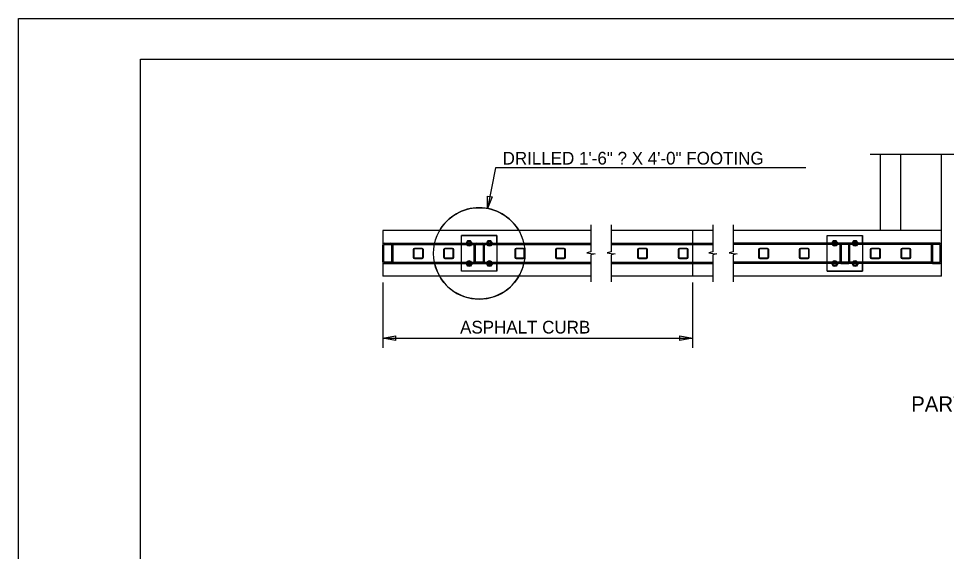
# Model space of a CAD drawing. Extents: x 0 to 22.7, y 0 to 15.8.
# Drawn here: x 0 to 7.61, y 10.3 to 14.67 of the extents above; entities that cross this region are included whole.
import ezdxf

# ---------------------------------------------------------------- set-up
doc = ezdxf.new("R2010")
doc.units = 0
for name, color, linetype in [('BORDER_ANNO_Cutsheet', 7, 'Continuous'), ('BRDG_ANNO_Anno-Sheet', 7, 'Continuous'), ('BRDG_ANNO_General-Notes', 7, 'Continuous'), ('BRDG_BASE_Hidden-Line', 7, 'Continuous'), ('BRDG_BASE_Obj-Line', 7, 'Continuous'), ('Default', 7, 'Continuous')]:
    doc.layers.add(name, color=color, linetype=linetype)

# ---------------------------------------------------------------- blocks, each defined once
blk = doc.blocks.new('TERM')
at = {"layer": 'Default'}
for p, q in [((-1.6, -0.27), (-1.6, 0.27)), ((-1.6, 0.27), (0, 0)), ((0, 0), (-1.6, -0.27))]:
    blk.add_line(p, q, dxfattribs=at)

msp = doc.modelspace()

# ---------------------------------------------------------------- linework, layer by layer
at = {"layer": 'BORDER_ANNO_Cutsheet'}
msp.add_lwpolyline([(0, 14.6667), (22.6667, 14.6667), (22.6667, 0), (0, 0)], close=True, dxfattribs=at)
at = {"layer": 'BRDG_ANNO_Anno-Sheet'}
msp.add_lwpolyline([(1, 14.3333), (22.3333, 14.3333), (22.3333, 0.3333), (1, 0.3333)], close=True, dxfattribs=at)
at = {"layer": 'BRDG_ANNO_General-Notes'}
for p, q in [((3.9117, 13.4436), (3.8487, 13.109)), ((6.4578, 13.4436), (3.9117, 13.4436)), ((3.8487, 13.2107), (3.8856, 13.2037)), ((3.8487, 13.109), (3.8487, 13.2107)), ((3.8856, 13.2037), (3.8487, 13.109)), ((2.9877, 12.5008), (2.9877, 11.9669)), ((5.5294, 12.5008), (5.5294, 11.9669)), ((2.9877, 12.0451), (5.5294, 12.0451))]:
    msp.add_line(p, q, dxfattribs=at)
at = {"layer": 'BRDG_BASE_Hidden-Line'}
for p, q in [((5.5294, 12.9071), (5.5294, 12.6571)), ((2.9877, 12.6727), (2.9877, 12.8081)), ((2.9981, 12.6727), (2.9981, 12.8081)), ((3.0033, 12.8238), (3.0554, 12.8238)), ((3.0033, 12.8133), (3.0554, 12.8133)), ((3.0554, 12.8133), (4.696, 12.8133)), ((3.0606, 12.8081), (3.0606, 12.6727)), ((3.071, 12.8081), (3.071, 12.6727)), ((3.7377, 12.6727), (3.7377, 12.8081)), ((3.7481, 12.6727), (3.7481, 12.8081)), ((3.7533, 12.8238), (3.8054, 12.8238)), ((3.7533, 12.8133), (3.8054, 12.8133)), ((3.8106, 12.8081), (3.8106, 12.6727)), ((3.821, 12.8081), (3.821, 12.6727)), ((4.8627, 12.8133), (5.696, 12.8133)), ((7.5033, 12.8133), (5.8627, 12.8133)), ((6.7377, 12.8081), (6.7377, 12.6727)), ((6.7481, 12.8081), (6.7481, 12.6727)), ((6.8054, 12.8238), (6.7533, 12.8238)), ((6.8054, 12.8133), (6.7533, 12.8133)), ((6.8106, 12.6727), (6.8106, 12.8081)), ((6.821, 12.6727), (6.821, 12.8081)), ((7.4877, 12.8081), (7.4877, 12.6727)), ((7.4981, 12.8081), (7.4981, 12.6727)), ((7.5554, 12.8238), (7.5033, 12.8238)), ((7.5554, 12.8133), (7.5033, 12.8133)), ((7.5606, 12.6727), (7.5606, 12.8081)), ((7.571, 12.6727), (7.571, 12.8081)), ((3.0554, 12.6675), (3.0033, 12.6675)), ((3.0554, 12.6571), (3.0033, 12.6571)), ((3.0554, 12.6675), (4.696, 12.6675)), ((3.8054, 12.6675), (3.7533, 12.6675)), ((3.8054, 12.6571), (3.7533, 12.6571)), ((4.8627, 12.6675), (5.696, 12.6675)), ((7.5033, 12.6675), (5.8627, 12.6675)), ((6.7533, 12.6675), (6.8054, 12.6675)), ((6.7533, 12.6571), (6.8054, 12.6571)), ((7.5033, 12.6675), (7.5554, 12.6675)), ((7.5033, 12.6571), (7.5554, 12.6571))]:
    msp.add_line(p, q, dxfattribs=at)
for points in [[(3.6335, 12.8863), (3.9252, 12.8863), (3.9252, 12.5946), (3.6335, 12.5946)], [(6.6335, 12.8863), (6.9252, 12.8863), (6.9252, 12.5946), (6.6335, 12.5946)]]:
    msp.add_lwpolyline(points, close=True, dxfattribs=at)
for points in [[(3.7204, 12.8238), (3.7082, 12.8449), (3.6838, 12.8449), (3.6716, 12.8238)], [(3.7204, 12.8238), (3.7082, 12.8026), (3.6838, 12.8026), (3.6716, 12.8238)], [(3.8871, 12.8238), (3.8749, 12.8449), (3.8505, 12.8449), (3.8382, 12.8238)], [(3.8871, 12.8238), (3.8749, 12.8026), (3.8505, 12.8026), (3.8382, 12.8238)], [(6.7204, 12.8238), (6.7082, 12.8449), (6.6838, 12.8449), (6.6716, 12.8238)], [(6.7204, 12.8238), (6.7082, 12.8026), (6.6838, 12.8026), (6.6716, 12.8238)], [(6.8871, 12.8238), (6.8749, 12.8449), (6.8505, 12.8449), (6.8382, 12.8238)], [(6.8871, 12.8238), (6.8749, 12.8026), (6.8505, 12.8026), (6.8382, 12.8238)], [(3.2377, 12.7717), (3.2377, 12.7092)], [(3.2429, 12.7717), (3.2429, 12.7092)], [(3.3106, 12.7821), (3.2481, 12.7821)], [(3.3106, 12.7769), (3.2481, 12.7769)], [(3.3158, 12.7092), (3.3158, 12.7717)], [(3.321, 12.7092), (3.321, 12.7717)], [(3.4877, 12.7717), (3.4877, 12.7092)], [(3.4929, 12.7717), (3.4929, 12.7092)], [(3.5606, 12.7821), (3.4981, 12.7821)], [(3.5606, 12.7769), (3.4981, 12.7769)], [(3.5658, 12.7092), (3.5658, 12.7717)], [(3.571, 12.7092), (3.571, 12.7717)], [(4.071, 12.7717), (4.071, 12.7092)], [(4.0762, 12.7717), (4.0762, 12.7092)], [(4.144, 12.7821), (4.0815, 12.7821)], [(4.144, 12.7769), (4.0815, 12.7769)], [(4.1492, 12.7092), (4.1492, 12.7717)], [(4.1544, 12.7092), (4.1544, 12.7717)], [(4.4044, 12.7717), (4.4044, 12.7092)], [(4.4096, 12.7717), (4.4096, 12.7092)], [(4.4773, 12.7821), (4.4148, 12.7821)], [(4.4773, 12.7769), (4.4148, 12.7769)], [(4.4825, 12.7092), (4.4825, 12.7717)], [(4.4877, 12.7092), (4.4877, 12.7717)], [(5.0777, 12.7717), (5.0777, 12.7092)], [(5.0829, 12.7717), (5.0829, 12.7092)], [(5.1506, 12.7821), (5.0881, 12.7821)], [(5.1506, 12.7769), (5.0881, 12.7769)], [(5.1558, 12.7092), (5.1558, 12.7717)], [(5.161, 12.7092), (5.161, 12.7717)], [(5.411, 12.7717), (5.411, 12.7092)], [(5.4162, 12.7717), (5.4162, 12.7092)], [(5.4839, 12.7821), (5.4214, 12.7821)], [(5.4839, 12.7769), (5.4214, 12.7769)], [(5.4891, 12.7092), (5.4891, 12.7717)], [(5.4943, 12.7092), (5.4943, 12.7717)], [(6.071, 12.7717), (6.071, 12.7092)], [(6.0762, 12.7717), (6.0762, 12.7092)], [(6.144, 12.7821), (6.0815, 12.7821)], [(6.144, 12.7769), (6.0815, 12.7769)], [(6.1492, 12.7092), (6.1492, 12.7717)], [(6.1544, 12.7092), (6.1544, 12.7717)], [(6.4044, 12.7717), (6.4044, 12.7092)], [(6.4096, 12.7717), (6.4096, 12.7092)], [(6.4773, 12.7821), (6.4148, 12.7821)], [(6.4773, 12.7769), (6.4148, 12.7769)], [(6.4825, 12.7092), (6.4825, 12.7717)], [(6.4877, 12.7092), (6.4877, 12.7717)], [(6.9877, 12.7717), (6.9877, 12.7092)], [(6.9929, 12.7717), (6.9929, 12.7092)], [(7.0606, 12.7821), (6.9981, 12.7821)], [(7.0606, 12.7769), (6.9981, 12.7769)], [(7.0658, 12.7092), (7.0658, 12.7717)], [(7.071, 12.7092), (7.071, 12.7717)], [(7.2377, 12.7717), (7.2377, 12.7092)], [(7.2429, 12.7717), (7.2429, 12.7092)], [(7.3106, 12.7821), (7.2481, 12.7821)], [(7.3106, 12.7769), (7.2481, 12.7769)], [(7.3158, 12.7092), (7.3158, 12.7717)], [(7.321, 12.7092), (7.321, 12.7717)], [(3.2481, 12.704), (3.3106, 12.704)], [(3.2481, 12.6988), (3.3106, 12.6988)], [(3.4981, 12.704), (3.5606, 12.704)], [(3.4981, 12.6988), (3.5606, 12.6988)], [(3.6716, 12.6571), (3.6838, 12.6782), (3.7082, 12.6782), (3.7204, 12.6571)], [(3.8382, 12.6571), (3.8505, 12.6782), (3.8749, 12.6782), (3.8871, 12.6571)], [(4.0815, 12.704), (4.144, 12.704)], [(4.0815, 12.6988), (4.144, 12.6988)], [(4.4148, 12.704), (4.4773, 12.704)], [(4.4148, 12.6988), (4.4773, 12.6988)], [(5.0881, 12.704), (5.1506, 12.704)], [(5.0881, 12.6988), (5.1506, 12.6988)], [(5.4214, 12.704), (5.4839, 12.704)], [(5.4214, 12.6988), (5.4839, 12.6988)], [(6.0815, 12.704), (6.144, 12.704)], [(6.0815, 12.6988), (6.144, 12.6988)], [(6.4148, 12.704), (6.4773, 12.704)], [(6.4148, 12.6988), (6.4773, 12.6988)], [(6.7204, 12.6571), (6.7082, 12.6782), (6.6838, 12.6782), (6.6716, 12.6571)], [(6.8871, 12.6571), (6.8749, 12.6782), (6.8505, 12.6782), (6.8382, 12.6571)], [(6.9981, 12.704), (7.0606, 12.704)], [(6.9981, 12.6988), (7.0606, 12.6988)], [(7.2481, 12.704), (7.3106, 12.704)], [(7.2481, 12.6988), (7.3106, 12.6988)]]:
    msp.add_lwpolyline(points, dxfattribs=at)
for centre, radius in [((3.7793, 12.7404), 0.375), ((3.696, 12.8238), 0.0143), ((3.8627, 12.8238), 0.0143), ((6.696, 12.8238), 0.0143), ((6.8627, 12.8238), 0.0143), ((3.696, 12.6571), 0.0143), ((3.8627, 12.6571), 0.0143), ((6.696, 12.6571), 0.0143), ((6.8627, 12.6571), 0.0143)]:
    msp.add_circle(centre, radius, dxfattribs=at)
for centre, radius, start, end in [((3.0033, 12.8081), 0.0156, 90, 180), ((3.0033, 12.8081), 0.00521, 90, 180), ((3.0554, 12.8081), 0.0156, 0, 90), ((3.0554, 12.8081), 0.00521, 0, 90), ((3.696, 12.8238), 0.0212, 0, 180), ((3.696, 12.8238), 0.0212, 180, 0), ((3.7533, 12.8081), 0.0156, 90, 180), ((3.7533, 12.8081), 0.00521, 90, 180), ((3.8054, 12.8081), 0.0156, 0, 90), ((3.8054, 12.8081), 0.00521, 0, 90), ((3.8627, 12.8238), 0.0212, 0, 180), ((3.8627, 12.8238), 0.0212, 180, 0), ((6.696, 12.8238), 0.0212, 0, 180), ((6.696, 12.8238), 0.0212, 180, 0), ((6.7533, 12.8081), 0.0156, 90, 180), ((6.7533, 12.8081), 0.00521, 90, 180), ((6.8054, 12.8081), 0.0156, 0, 90), ((6.8054, 12.8081), 0.00521, 0, 90), ((6.8627, 12.8238), 0.0212, 0, 180), ((6.8627, 12.8238), 0.0212, 180, 0), ((7.5033, 12.8081), 0.0156, 90, 180), ((7.5033, 12.8081), 0.00521, 90, 180), ((7.5554, 12.8081), 0.0156, 0, 90), ((7.5554, 12.8081), 0.00521, 0, 90), ((3.2481, 12.7717), 0.0104, 90, 180), ((3.2481, 12.7717), 0.00521, 90, 180), ((3.3106, 12.7717), 0.0104, 0, 90), ((3.3106, 12.7717), 0.00521, 0, 90), ((3.4981, 12.7717), 0.0104, 90, 180), ((3.4981, 12.7717), 0.00521, 90, 180), ((3.5606, 12.7717), 0.0104, 0, 90), ((3.5606, 12.7717), 0.00521, 0, 90), ((4.0815, 12.7717), 0.0104, 90, 180), ((4.0815, 12.7717), 0.00521, 90, 180), ((4.144, 12.7717), 0.0104, 0, 90), ((4.144, 12.7717), 0.00521, 0, 90), ((4.4148, 12.7717), 0.0104, 90, 180), ((4.4148, 12.7717), 0.00521, 90, 180), ((4.4773, 12.7717), 0.0104, 0, 90), ((4.4773, 12.7717), 0.00521, 0, 90), ((5.0881, 12.7717), 0.0104, 90, 180), ((5.0881, 12.7717), 0.00521, 90, 180), ((5.1506, 12.7717), 0.0104, 0, 90), ((5.1506, 12.7717), 0.00521, 0, 90), ((5.4214, 12.7717), 0.0104, 90, 180), ((5.4214, 12.7717), 0.00521, 90, 180), ((5.4839, 12.7717), 0.0104, 0, 90), ((5.4839, 12.7717), 0.00521, 0, 90), ((6.0815, 12.7717), 0.0104, 90, 180), ((6.0815, 12.7717), 0.00521, 90, 180), ((6.144, 12.7717), 0.0104, 0, 90), ((6.144, 12.7717), 0.00521, 0, 90), ((6.4148, 12.7717), 0.0104, 90, 180), ((6.4148, 12.7717), 0.00521, 90, 180), ((6.4773, 12.7717), 0.0104, 0, 90), ((6.4773, 12.7717), 0.00521, 0, 90), ((6.9981, 12.7717), 0.0104, 90, 180), ((6.9981, 12.7717), 0.00521, 90, 180), ((7.0606, 12.7717), 0.0104, 0, 90), ((7.0606, 12.7717), 0.00521, 0, 90), ((7.2481, 12.7717), 0.0104, 90, 180), ((7.2481, 12.7717), 0.00521, 90, 180), ((7.3106, 12.7717), 0.0104, 0, 90), ((7.3106, 12.7717), 0.00521, 0, 90), ((3.0033, 12.6727), 0.0156, 180, 270), ((3.0033, 12.6727), 0.00521, 180, 270), ((3.0554, 12.6727), 0.00521, 270, 0), ((3.0554, 12.6727), 0.0156, 270, 0), ((3.2481, 12.7092), 0.0104, 180, 270), ((3.2481, 12.7092), 0.00521, 180, 270), ((3.3106, 12.7092), 0.0104, 270, 0), ((3.3106, 12.7092), 0.00521, 270, 0), ((3.4981, 12.7092), 0.0104, 180, 270), ((3.4981, 12.7092), 0.00521, 180, 270), ((3.5606, 12.7092), 0.0104, 270, 0), ((3.5606, 12.7092), 0.00521, 270, 0), ((3.696, 12.6571), 0.0212, 0, 179.99998), ((3.7533, 12.6727), 0.0156, 180, 270), ((3.7533, 12.6727), 0.00521, 180, 270), ((3.8054, 12.6727), 0.00521, 270, 0), ((3.8054, 12.6727), 0.0156, 270, 0), ((3.8627, 12.6571), 0.0212, 0, 179.99998), ((4.0815, 12.7092), 0.0104, 180, 270), ((4.0815, 12.7092), 0.00521, 180, 270), ((4.144, 12.7092), 0.0104, 270, 0), ((4.144, 12.7092), 0.00521, 270, 0), ((4.4148, 12.7092), 0.0104, 180, 270), ((4.4148, 12.7092), 0.00521, 180, 270), ((4.4773, 12.7092), 0.0104, 270, 0), ((4.4773, 12.7092), 0.00521, 270, 0), ((5.0881, 12.7092), 0.0104, 180, 270), ((5.0881, 12.7092), 0.00521, 180, 270), ((5.1506, 12.7092), 0.0104, 270, 0), ((5.1506, 12.7092), 0.00521, 270, 0), ((5.4214, 12.7092), 0.0104, 180, 270), ((5.4214, 12.7092), 0.00521, 180, 270), ((5.4839, 12.7092), 0.0104, 270, 0), ((5.4839, 12.7092), 0.00521, 270, 0), ((6.0815, 12.7092), 0.0104, 180, 270), ((6.0815, 12.7092), 0.00521, 180, 270), ((6.144, 12.7092), 0.0104, 270, 0), ((6.144, 12.7092), 0.00521, 270, 0), ((6.4148, 12.7092), 0.0104, 180, 270), ((6.4148, 12.7092), 0.00521, 180, 270), ((6.4773, 12.7092), 0.0104, 270, 0), ((6.4773, 12.7092), 0.00521, 270, 0), ((6.696, 12.6571), 0.0212, 0, 180), ((6.7533, 12.6727), 0.0156, 180, 270), ((6.7533, 12.6727), 0.00521, 180, 270), ((6.8054, 12.6727), 0.00521, 270, 0), ((6.8054, 12.6727), 0.0156, 270, 0), ((6.8627, 12.6571), 0.0212, 0, 180), ((6.9981, 12.7092), 0.0104, 180, 270), ((6.9981, 12.7092), 0.00521, 180, 270), ((7.0606, 12.7092), 0.0104, 270, 0), ((7.0606, 12.7092), 0.00521, 270, 0), ((7.2481, 12.7092), 0.0104, 180, 270), ((7.2481, 12.7092), 0.00521, 180, 270), ((7.3106, 12.7092), 0.0104, 270, 0), ((7.3106, 12.7092), 0.00521, 270, 0), ((7.5033, 12.6727), 0.0156, 180, 270), ((7.5033, 12.6727), 0.00521, 180, 270), ((7.5554, 12.6727), 0.00521, 270, 0), ((7.5554, 12.6727), 0.0156, 270, 0)]:
    msp.add_arc(centre, radius, start, end, dxfattribs=at)
at = {"layer": 'BRDG_BASE_Obj-Line'}
for p, q in [((7.071, 12.9279), (7.071, 13.5529)), ((7.2377, 12.9279), (7.2377, 13.5529)), ((7.571, 12.5529), (7.571, 13.5529)), ((4.696, 12.9279), (2.9877, 12.9279)), ((2.9877, 12.9279), (2.9877, 12.5529)), ((3.9252, 12.8863), (3.6335, 12.8863)), ((3.6335, 12.8238), (3.6335, 12.8863)), ((3.9252, 12.8238), (3.9252, 12.8863)), ((5.5294, 12.9279), (4.8627, 12.9279)), ((5.5294, 12.9279), (5.5294, 12.8238)), ((5.696, 12.9279), (5.5294, 12.9279)), ((7.571, 12.9279), (5.8627, 12.9279)), ((6.6335, 12.8863), (6.9252, 12.8863)), ((6.6335, 12.8238), (6.6335, 12.8863)), ((6.9252, 12.8238), (6.9252, 12.8863)), ((2.9877, 12.6727), (2.9877, 12.8081)), ((2.9981, 12.8238), (4.696, 12.8238)), ((4.8627, 12.8238), (5.696, 12.8238)), ((7.5606, 12.8238), (5.8627, 12.8238)), ((7.571, 12.6727), (7.571, 12.8081)), ((3.0033, 12.6571), (4.696, 12.6571)), ((3.6335, 12.5946), (3.6335, 12.6571)), ((3.9252, 12.5946), (3.9252, 12.6571)), ((4.8627, 12.6571), (5.696, 12.6571)), ((5.5294, 12.6571), (5.5294, 12.5529)), ((7.5554, 12.6571), (5.8627, 12.6571)), ((6.6335, 12.5946), (6.6335, 12.6571)), ((6.9252, 12.5946), (6.9252, 12.6571)), ((3.9252, 12.5946), (3.6335, 12.5946)), ((6.6335, 12.5946), (6.9252, 12.5946)), ((4.696, 12.5529), (2.9877, 12.5529)), ((5.5294, 12.5529), (4.8627, 12.5529)), ((5.696, 12.5529), (5.5294, 12.5529)), ((7.571, 12.5529), (5.8627, 12.5529))]:
    msp.add_line(p, q, dxfattribs=at)
for points in [[(8.4669, 13.5529), (7.7669, 13.5529), (7.7405, 13.6586), (7.7273, 13.5529), (7.7141, 13.4472), (7.6876, 13.5529), (6.9877, 13.5529)], [(4.696, 12.9737), (4.696, 12.7529), (4.6627, 12.7446), (4.696, 12.7404), (4.7294, 12.7363), (4.696, 12.7279), (4.696, 12.5071)], [(4.8627, 12.9737), (4.8627, 12.7529), (4.8294, 12.7446), (4.8627, 12.7404), (4.896, 12.7363), (4.8627, 12.7279), (4.8627, 12.5071)], [(5.696, 12.9737), (5.696, 12.7529), (5.6627, 12.7446), (5.696, 12.7404), (5.7294, 12.7363), (5.696, 12.7279), (5.696, 12.5071)], [(5.8627, 12.9737), (5.8627, 12.7529), (5.8294, 12.7446), (5.8627, 12.7404), (5.896, 12.7363), (5.8627, 12.7279), (5.8627, 12.5071)], [(3.7204, 12.8238), (3.7082, 12.8449), (3.6838, 12.8449), (3.6716, 12.8238)], [(3.8871, 12.8238), (3.8749, 12.8449), (3.8505, 12.8449), (3.8382, 12.8238)], [(6.7204, 12.8238), (6.7082, 12.8449), (6.6838, 12.8449), (6.6716, 12.8238)], [(6.8871, 12.8238), (6.8749, 12.8449), (6.8505, 12.8449), (6.8382, 12.8238)], [(3.7204, 12.6571), (3.7082, 12.6359), (3.6838, 12.6359), (3.6716, 12.6571)], [(3.8871, 12.6571), (3.8749, 12.6359), (3.8505, 12.6359), (3.8382, 12.6571)], [(6.7204, 12.6571), (6.7082, 12.6359), (6.6838, 12.6359), (6.6716, 12.6571)], [(6.8871, 12.6571), (6.8749, 12.6359), (6.8505, 12.6359), (6.8382, 12.6571)]]:
    msp.add_lwpolyline(points, dxfattribs=at)
for centre, radius, start, end in [((3.7793, 12.7404), 0.375, 30, 150), ((3.0033, 12.8081), 0.0156, 90, 180), ((3.696, 12.8238), 0.0212, 0, 180), ((3.8627, 12.8238), 0.0212, 0, 180), ((6.696, 12.8238), 0.0212, 0, 180), ((6.8627, 12.8238), 0.0212, 0, 180), ((7.5554, 12.8081), 0.0156, 0, 90), ((3.0033, 12.6727), 0.0156, 180, 270), ((3.7793, 12.7404), 0.375, 192.83959, 347.16041), ((3.696, 12.6571), 0.0212, 180, 0), ((3.8627, 12.6571), 0.0212, 180, 0), ((6.696, 12.6571), 0.0212, 180, 0), ((6.8627, 12.6571), 0.0212, 180, 0), ((7.5554, 12.6727), 0.0156, 270, 360)]:
    msp.add_arc(centre, radius, start, end, dxfattribs=at)

# ---------------------------------------------------------------- block references
at = {"layer": 'BRDG_ANNO_General-Notes', "xscale": 0.06510416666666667, "yscale": 0.0732421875, "rotation": 180}
msp.add_blockref('TERM', (2.9877, 12.0451), dxfattribs=at)
at = {"layer": 'BRDG_ANNO_General-Notes', "xscale": 0.06510416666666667, "yscale": 0.0732421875}
msp.add_blockref('TERM', (5.5294, 12.0451), dxfattribs=at)

# ---------------------------------------------------------------- texts
at = {"layer": 'BRDG_ANNO_General-Notes'}
for s, height, p in [('DRILLED 1\'-6" ? X 4\'-0" FOOTING', 0.104167, (3.9714, 13.4692)), ('ASPHALT CURB', 0.104167, (3.6225, 12.0836)), ('PARTIAL PLAN', 0.125, (7.3235, 11.4428))]:
    msp.add_text(s, height=height, dxfattribs=at).set_placement(p)

doc.saveas('drawing.dxf')
